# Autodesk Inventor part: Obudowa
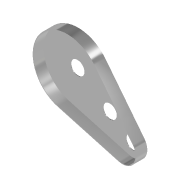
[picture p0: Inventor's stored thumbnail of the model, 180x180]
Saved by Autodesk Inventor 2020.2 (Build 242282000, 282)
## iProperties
Created: 2014-01
Part Number: Obudowa
Material: Ogólny
Document SubType Name: Modeling
Designer: F.Stasiak
Density: 1 g/cm^3
Appearance: Chrom - polerowany
Manager: www.cadconsulting.pl
Company: Fabian Stasiak CAD Consulting
Author: F.Stasiak
Subject: Zbiór ćwiczeń. Autodesk Inventor 2020. Kurs podstawowy
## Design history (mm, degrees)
sketch "Szkic1"
  geometry: L1 (28.833, 66.572)-(205.183, 17.529); L2 (134.254, 224.703)-(247.351, 80.781); C1 r 15 at (55.627, 162.916) reference; C2 r 15 at (149.336, 100.442) reference; C3 r 15 at (215.9, 56.066) reference; C4 r 20 at (55.627, 162.916); C5 r 20 at (215.9, 56.066); A1 r 100 centre (55.627, 162.916) between (134.254, 224.703) and (28.833, 66.572); A2 r 40 centre (215.9, 56.066) between (205.183, 17.529) and (247.351, 80.781); A3 r 100 centre (55.627, 162.916) between (146.029, 120.167) and (134.254, 224.703); A4 r 100 centre (55.627, 162.916) between (28.833, 66.572) and (146.029, 120.167); A5 r 40 centre (215.9, 56.066) between (247.351, 80.781) and (205.183, 17.529); 1 further point
  constraints: 10 point on circle, 7 centre point, 6 tangent, 4 end point, 2 coincident, 5 other
  dimensions: "d0" = 40 diameter of C4; "d1" = 200 diameter of A1; "d2" = 80 diameter of A2
extrude "Wyciągnięcie proste1" new body sketch "Szkic1" distance "d3" = 32; taper "d4" = 0 deg
feature "Skorupa1" dims "d5" = 2
node "Bryła1"
node "Odniesienie1"
node "Odniesienie2"
node "Odniesienie3"
